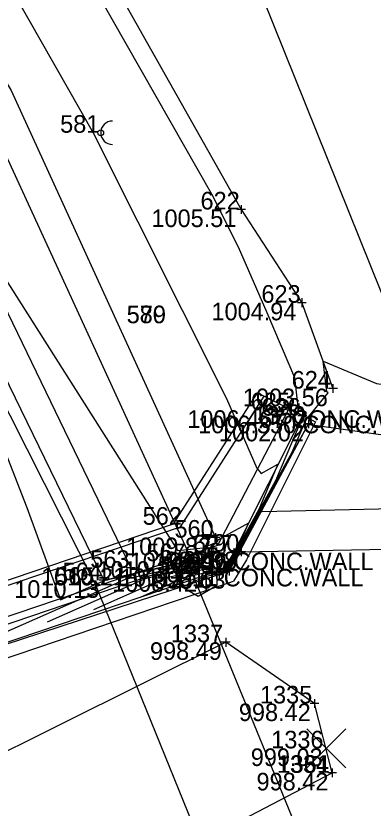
# Model space of a CAD drawing. Extents: x 2354693 to 2355622, y 637071 to 710080.
# Drawn here: x 2355337.5 to 2355361.9, y 709334.6 to 709388.6 of the extents above; entities that cross this region are included whole.
import ezdxf

# ---------------------------------------------------------------- set-up
doc = ezdxf.new("R2010")
doc.units = 0
for name, color, linetype in [('BR_X_Sub_Foot_Object', 7, 'Continuous'), ('BR_X_SV_Abut', 7, 'Continuous'), ('BR_X_SV_Beam_Seat', 7, 'Continuous'), ('DT_X_Contour_Major', 7, 'Continuous'), ('DT_X_Contour_Minor', 7, 'Continuous'), ('HY_X_Water_Edge', 7, 'Continuous'), ('PM_X_Surveyed_Line', 7, 'Continuous'), ('PV_X_EOP', 7, 'Continuous'), ('PV_X_Shoulder', 7, 'Continuous'), ('RD_X_Cells', 7, 'Continuous'), ('RD_X_GR_Lt', 7, 'Continuous'), ('SV_X_Break_Lines', 7, 'Continuous'), ('SV_X_Random_Point', 7, 'Continuous'), ('SV_X_Shot_Marker', 7, 'Continuous'), ('SV_X_Text_Comment', 7, 'Continuous'), ('SV_X_Text_Elevation', 7, 'Continuous'), ('SV_X_Text_Name', 7, 'Continuous'), ('SV_X_Toe_of_Slope', 7, 'Continuous'), ('SV_X_Top_of_Bank', 7, 'Continuous'), ('UT_X_Misc_Cells', 7, 'Continuous'), ('UT_X_Telecom', 7, 'Continuous')]:
    doc.layers.add(name, color=color, linetype=linetype)

msp = doc.modelspace()

# ---------------------------------------------------------------- linework, layer by layer
at = {"layer": 'BR_X_Sub_Foot_Object'}
for p, q in [((2355348.286, 709353.939), (2355354.026, 709362.886)), ((2355348.756, 709353.746), (2355354.475, 709362.661)), ((2355354.026, 709362.886), (2355357.991, 709360.898)), ((2355320.058, 709344.378), (2355348.286, 709353.939)), ((2355319.807, 709343.941), (2355348.756, 709353.746)), ((2355320.484, 709339.244), (2355352.382, 709350.047))]:
    msp.add_line(p, q, dxfattribs=at)
msp.add_lwpolyline([(2355357.991, 709360.898), (2355353.278, 709351.501), (2355352.382, 709350.047)], dxfattribs=at)
at = {"layer": 'BR_X_SV_Abut'}
for p, q in [((2355351.31, 709352.499), (2355356.173, 709361.771)), ((2355319.736, 709341.806), (2355351.31, 709352.499)), ((2355319.789, 709341.296), (2355351.346, 709351.984)), ((2355320.164, 709340.191), (2355351.72, 709350.879))]:
    msp.add_line(p, q, dxfattribs=at)
msp.add_lwpolyline([(2355356.328, 709361.694), (2355357.086, 709361.324), (2355352.404, 709351.988), (2355351.72, 709350.879)], dxfattribs=at)
at = {"layer": 'BR_X_SV_Beam_Seat'}
for p, q in [((2355352.404, 709352.288), (2355352.404, 709351.688)), ((2355352.704, 709351.988), (2355352.104, 709351.988)), ((2355351.222, 709350.815), (2355351.222, 709350.215)), ((2355351.522, 709350.515), (2355350.922, 709350.515))]:
    msp.add_line(p, q, dxfattribs=at)
at = {"layer": 'DT_X_Contour_Major'}
for points in [[(2355329.768, 709376.874), (2355338.272, 709355.053), (2355340.574, 709348.757), (2355343.616, 709350.102)], [(2355329.768, 709376.874), (2355338.272, 709355.053), (2355340.574, 709348.757), (2355343.616, 709350.102)], [(2355343.616, 709350.102), (2355349.258, 709351.382), (2355351.694, 709350.839), (2355351.75, 709350.866), (2355352.378, 709351.887), (2355352.97, 709352.962), (2355353.407, 709353.989), (2355351.34, 709352.861), (2355351.242, 709352.706), (2355350.295, 709352.289), (2355348.6, 709352.094), (2355333.866, 709375.297)], [(2355343.616, 709350.102), (2355349.258, 709351.382), (2355351.694, 709350.839), (2355351.75, 709350.866), (2355352.378, 709351.887), (2355352.97, 709352.962), (2355353.407, 709353.989), (2355351.34, 709352.861), (2355351.242, 709352.706), (2355350.295, 709352.289), (2355348.6, 709352.094), (2355333.866, 709375.297)], [(2355349.216, 709349.807), (2355350.46, 709350.357), (2355351.14, 709350.511), (2355351.433, 709350.446), (2355352.043, 709350.744), (2355352.119, 709350.867), (2355354.278, 709354.787), (2355354.352, 709354.784), (2355372.217, 709355.195), (2355377.397, 709354.455), (2355381.095, 709354.556), (2355411.836, 709365.805), (2355413.019, 709366.158), (2355415.355, 709371.884), (2355426.88, 709369.542), (2355418.722, 709358.718)], [(2355349.216, 709349.807), (2355350.46, 709350.357), (2355351.14, 709350.511), (2355351.433, 709350.446), (2355352.043, 709350.744), (2355352.119, 709350.867), (2355354.278, 709354.787), (2355354.352, 709354.784), (2355372.217, 709355.195), (2355377.397, 709354.455), (2355381.095, 709354.556), (2355411.836, 709365.805), (2355413.019, 709366.158), (2355415.355, 709371.884), (2355426.88, 709369.542), (2355418.722, 709358.718)]]:
    msp.add_lwpolyline(points, dxfattribs=at)
at = {"layer": 'DT_X_Contour_Minor'}
for points in [[(2355256.514, 709490.43), (2355283.775, 709461.072), (2355292.628, 709451.208), (2355294.845, 709448.841), (2355297.747, 709446.107), (2355326.872, 709414.967), (2355331.388, 709409.92), (2355333.438, 709407.016), (2355350.907, 709376.422), (2355352.705, 709372.844), (2355354.66, 709368.362), (2355356.548, 709363.933), (2355356.786, 709361.932), (2355357.348, 709361.556), (2355357.12, 709361.279), (2355355.247, 709356.875), (2355352.274, 709351.479), (2355351.867, 709350.817), (2355351.589, 709350.682), (2355350.011, 709351.034), (2355346.353, 709350.204), (2355339.665, 709347.247)], [(2355256.514, 709490.43), (2355283.775, 709461.072), (2355292.628, 709451.208), (2355294.845, 709448.841), (2355297.747, 709446.107), (2355326.872, 709414.967), (2355331.388, 709409.92), (2355333.438, 709407.016), (2355350.907, 709376.422), (2355352.705, 709372.844), (2355354.66, 709368.362), (2355356.548, 709363.933), (2355356.786, 709361.932), (2355357.348, 709361.556), (2355357.12, 709361.279), (2355355.247, 709356.875), (2355352.274, 709351.479), (2355351.867, 709350.817), (2355351.589, 709350.682), (2355350.011, 709351.034), (2355346.353, 709350.204), (2355339.665, 709347.247)], [(2355255.69, 709482.934), (2355288.364, 709446.527), (2355296.545, 709437.792), (2355301.822, 709432.821), (2355307.383, 709427.211), (2355308.607, 709426.123), (2355326.354, 709406.292), (2355335.671, 709393.094), (2355342.795, 709380.617), (2355351.9, 709362.495), (2355353.976, 709357.738), (2355354.28, 709357.384), (2355355.423, 709358.007), (2355354.109, 709354.918), (2355352.326, 709351.683), (2355351.808, 709350.842), (2355351.641, 709350.76), (2355349.634, 709351.208), (2355344.985, 709350.153), (2355336.482, 709346.393)], [(2355255.69, 709482.934), (2355288.364, 709446.527), (2355296.545, 709437.792), (2355301.822, 709432.821), (2355307.383, 709427.211), (2355308.607, 709426.123), (2355326.354, 709406.292), (2355335.671, 709393.094), (2355342.795, 709380.617), (2355351.9, 709362.495), (2355353.976, 709357.738), (2355354.28, 709357.384), (2355355.423, 709358.007), (2355354.109, 709354.918), (2355352.326, 709351.683), (2355351.808, 709350.842), (2355351.641, 709350.76), (2355349.634, 709351.208), (2355344.985, 709350.153), (2355336.482, 709346.393)], [(2355346.033, 709348.954), (2355349.091, 709350.306), (2355350.763, 709350.685), (2355351.485, 709350.524), (2355351.985, 709350.769), (2355352.171, 709351.071), (2355357.489, 709360.726), (2355357.49, 709360.726), (2355357.63, 709360.729), (2355373.499, 709358.462), (2355384.828, 709358.77), (2355406.085, 709366.548), (2355412.097, 709368.343), (2355414.408, 709374.007), (2355418.626, 709378.122), (2355431.615, 709394.262), (2355434.67, 709399.067), (2355441.725, 709407.886)], [(2355346.033, 709348.954), (2355349.091, 709350.306), (2355350.763, 709350.685), (2355351.485, 709350.524), (2355351.985, 709350.769), (2355352.171, 709351.071), (2355357.489, 709360.726), (2355357.49, 709360.726), (2355357.63, 709360.729), (2355373.499, 709358.462), (2355384.828, 709358.77), (2355406.085, 709366.548), (2355412.097, 709368.343), (2355414.408, 709374.007), (2355418.626, 709378.122), (2355431.615, 709394.262), (2355434.67, 709399.067), (2355441.725, 709407.886)], [(2355342.849, 709348.1), (2355347.722, 709350.255), (2355350.387, 709350.859), (2355351.537, 709350.603), (2355351.926, 709350.793), (2355352.223, 709351.275), (2355356.385, 709358.831), (2355357.318, 709361.025), (2355358.848, 709362.883), (2355358.748, 709362.951), (2355358.5, 709365.034), (2355362.15, 709363.512), (2355364.815, 709363.153), (2355369.602, 709362.469), (2355388.561, 709362.984), (2355400.334, 709367.291), (2355411.176, 709370.528), (2355412.756, 709374.401), (2355421.504, 709382.936), (2355430.17, 709393.705), (2355436.389, 709403.486)], [(2355342.849, 709348.1), (2355347.722, 709350.255), (2355350.387, 709350.859), (2355351.537, 709350.603), (2355351.926, 709350.793), (2355352.223, 709351.275), (2355356.385, 709358.831), (2355357.318, 709361.025), (2355358.848, 709362.883), (2355358.748, 709362.951), (2355358.5, 709365.034), (2355362.15, 709363.512), (2355364.815, 709363.153), (2355369.602, 709362.469), (2355388.561, 709362.984), (2355400.334, 709367.291), (2355411.176, 709370.528), (2355412.756, 709374.401), (2355421.504, 709382.936), (2355430.17, 709393.705), (2355436.389, 709403.486)]]:
    msp.add_lwpolyline(points, dxfattribs=at)
at = {"layer": 'HY_X_Water_Edge'}
for points in [[(2355352.907, 709352.047), (2355379.285, 709352.514), (2355413.245, 709365.623), (2355415.947, 709373.639), (2355433.01, 709394.801), (2355445.631, 709410.589)], [(2355359.12, 709336.962), (2355357.913, 709341.692), (2355351.852, 709345.867), (2355323.23, 709331.642), (2355296.554, 709310.152), (2355279.902, 709286.977), (2355296.129, 709295.23), (2355310.102, 709295.061), (2355327.095, 709303.904), (2355323.879, 709317.989), (2355329.602, 709321.567), (2355359.12, 709336.962)]]:
    msp.add_lwpolyline(points, dxfattribs=at)
at = {"layer": 'PM_X_Surveyed_Line'}
msp.add_lwpolyline([(2355180.148, 709561.237), (2355214.753, 709522.888), (2355249.307, 709484.271), (2355284.017, 709443.142), (2355315.552, 709399.77), (2355328.888, 709377.573), (2355342.967, 709349.789), (2355353.365, 709324.191), (2355361.351, 709299.648), (2355367.764, 709272.473), (2355372.191, 709243.487), (2355373.87, 709217.884), (2355371.213, 709164.414), (2355367.135, 709139.625), (2355360.061, 709111.877), (2355351.618, 709085.78), (2355342.505, 709062.338), (2355329.445, 709031.419), (2355320.624, 709012.583)], dxfattribs=at)
at = {"layer": 'PV_X_EOP'}
msp.add_lwpolyline([(2355180.814, 709561.741), (2355215.64, 709523.556), (2355249.922, 709484.356), (2355284.407, 709443.36), (2355315.939, 709399.966), (2355329.751, 709378.355), (2355343.524, 709350.098), (2355349.219, 709351.4), (2355359.304, 709326.795), (2355367.588, 709301.754), (2355374.108, 709275.907), (2355368.17, 709272.694), (2355372.498, 709243.563), (2355374.502, 709217.665), (2355371.414, 709164.432), (2355367.842, 709139.325), (2355361.02, 709111.642), (2355352.388, 709085.56), (2355343.445, 709061.967), (2355330.49, 709031.083), (2355321.141, 709011.801)], dxfattribs=at)
at = {"layer": 'PV_X_Shoulder'}
msp.add_lwpolyline([(2355182.191, 709563.218), (2355217.156, 709524.646), (2355251.587, 709486.128), (2355286.914, 709444.936), (2355318.238, 709401.514), (2355331.465, 709379.667), (2355345.367, 709350.943)], dxfattribs=at)
at = {"layer": 'RD_X_Cells'}
msp.add_lwpolyline([(2355348.682, 709349.774), (2355349.98, 709349.024), (2355351.278, 709349.774), (2355351.278, 709351.274), (2355349.98, 709352.024), (2355348.682, 709351.274), (2355348.682, 709349.774)], dxfattribs=at)
at = {"layer": 'RD_X_GR_Lt'}
msp.add_lwpolyline([(2355298.604, 709438.975), (2355313.711, 709417.638), (2355322.758, 709404.112), (2355335.403, 709382.171), (2355349.98, 709350.524)], dxfattribs=at)
at = {"layer": 'SV_X_Break_Lines'}
msp.add_lwpolyline([(2355313.178, 709343.449), (2355320.081, 709340.268), (2355352.083, 709350.728), (2355357.514, 709360.772)], dxfattribs=at)
at = {"layer": 'SV_X_Random_Point'}
for p, q in [((2355357.384, 709337.293), (2355360.051, 709339.963)), ((2355357.384, 709339.963), (2355360.051, 709337.293))]:
    msp.add_line(p, q, dxfattribs=at)
at = {"layer": 'SV_X_Shot_Marker'}
for p, q in [((2355352.903, 709375.69), (2355352.903, 709375.09)), ((2355353.203, 709375.39), (2355352.603, 709375.39)), ((2355357.35, 709369.03), (2355356.75, 709369.03)), ((2355357.05, 709369.33), (2355357.05, 709368.73)), ((2355359.476, 709363.173), (2355358.876, 709363.173)), ((2355359.176, 709363.473), (2355359.176, 709362.873)), ((2355356.328, 709361.994), (2355356.328, 709361.394)), ((2355356.328, 709361.994), (2355356.328, 709361.394)), ((2355356.628, 709361.694), (2355356.028, 709361.694)), ((2355356.628, 709361.694), (2355356.028, 709361.694)), ((2355357.086, 709361.624), (2355357.086, 709361.024)), ((2355357.086, 709361.624), (2355357.086, 709361.024)), ((2355357.386, 709361.324), (2355356.786, 709361.324)), ((2355357.386, 709361.324), (2355356.786, 709361.324)), ((2355357.514, 709361.073), (2355357.514, 709360.472)), ((2355357.814, 709360.772), (2355357.214, 709360.772)), ((2355351.163, 709353.306), (2355351.163, 709352.706)), ((2355351.463, 709353.006), (2355350.863, 709353.006)), ((2355351.16, 709352.236), (2355350.56, 709352.236)), ((2355351.266, 709352.277), (2355350.666, 709352.277)), ((2355350.86, 709352.536), (2355350.86, 709351.936)), ((2355350.966, 709352.577), (2355350.966, 709351.977)), ((2355352.404, 709352.288), (2355352.404, 709351.688)), ((2355352.907, 709352.347), (2355352.907, 709351.747)), ((2355349.219, 709351.7), (2355349.219, 709351.1)), ((2355349.289, 709351.84), (2355349.289, 709351.24)), ((2355352.704, 709351.988), (2355352.104, 709351.988)), ((2355353.207, 709352.047), (2355352.607, 709352.047)), ((2355345.367, 709351.243), (2355345.367, 709350.643)), ((2355349.519, 709351.4), (2355348.919, 709351.4)), ((2355349.589, 709351.54), (2355348.989, 709351.54)), ((2355351.72, 709351.179), (2355351.72, 709350.579)), ((2355351.72, 709351.179), (2355351.72, 709350.579)), ((2355345.667, 709350.943), (2355345.067, 709350.943)), ((2355351.416, 709350.779), (2355351.416, 709350.178)), ((2355351.416, 709350.779), (2355351.416, 709350.178)), ((2355352.02, 709350.879), (2355351.42, 709350.879)), ((2355352.02, 709350.879), (2355351.42, 709350.879)), ((2355352.383, 709350.728), (2355351.783, 709350.728)), ((2355352.083, 709351.028), (2355352.083, 709350.428)), ((2355342.967, 709350.089), (2355342.967, 709349.489)), ((2355343.824, 709350.098), (2355343.224, 709350.098)), ((2355343.524, 709350.398), (2355343.524, 709349.798)), ((2355351.716, 709350.478), (2355351.116, 709350.478)), ((2355351.716, 709350.478), (2355351.116, 709350.478)), ((2355343.267, 709349.789), (2355342.667, 709349.789)), ((2355352.152, 709345.867), (2355351.552, 709345.867)), ((2355351.852, 709346.167), (2355351.852, 709345.567)), ((2355357.913, 709341.992), (2355357.913, 709341.392)), ((2355358.213, 709341.692), (2355357.613, 709341.692)), ((2355359.12, 709337.262), (2355359.12, 709336.662)), ((2355359.12, 709337.262), (2355359.12, 709336.662)), ((2355359.42, 709336.962), (2355358.82, 709336.962)), ((2355359.42, 709336.962), (2355358.82, 709336.962))]:
    msp.add_line(p, q, dxfattribs=at)
at = {"layer": 'SV_X_Toe_of_Slope'}
for points in [[(2355187.561, 709568.549), (2355223.434, 709529.363), (2355257.658, 709491.428), (2355294.213, 709452.947), (2355332.808, 709410.944), (2355352.903, 709375.39), (2355357.05, 709369.03), (2355359.176, 709363.173)], [(2355352.907, 709352.047), (2355379.285, 709352.514), (2355413.245, 709365.623), (2355415.947, 709373.639), (2355433.01, 709394.801), (2355445.631, 709410.589)], [(2355359.12, 709336.962), (2355357.913, 709341.692), (2355351.852, 709345.867), (2355323.23, 709331.642), (2355296.554, 709310.152), (2355279.902, 709286.977), (2355296.129, 709295.23), (2355310.102, 709295.061), (2355327.095, 709303.904), (2355323.879, 709317.989), (2355329.602, 709321.567), (2355359.12, 709336.962)]]:
    msp.add_lwpolyline(points, dxfattribs=at)
at = {"layer": 'SV_X_Top_of_Bank'}
msp.add_lwpolyline([(2355296.627, 709437.256), (2355306.813, 709428.559), (2355324.299, 709404.811), (2355337.209, 709383.506), (2355351.163, 709353.006)], dxfattribs=at)
at = {"layer": 'UT_X_Misc_Cells'}
msp.add_circle((2355343.319, 709380.623), 0.2, dxfattribs=at)
msp.add_arc((2355344.119, 709380.623), 0.8, 90, 270, dxfattribs=at)
at = {"layer": 'UT_X_Telecom'}
msp.add_line((2355345.904, 709410.895), (2355420.443, 709225.551), dxfattribs=at)

# ---------------------------------------------------------------- texts
at = {"layer": 'BR_X_SV_Beam_Seat'}
for s, p in [('627', (2355349.617, 709351.988)), ('1010.996', (2355345.296, 709350.788)), ('1330', (2355347.456, 709350.515)), ('CONC.WALL', (2355352.404, 709350.788)), ('1008.424', (2355344.094, 709349.315))]:
    msp.add_text(s, height=1.2, dxfattribs=at).set_placement(p)
at = {"layer": 'SV_X_Text_Comment'}
for p in [(2355356.328, 709360.494), (2355357.086, 709360.124), (2355351.72, 709349.679)]:
    msp.add_text('CONC.WALL', height=1.2, dxfattribs=at).set_placement(p)
at = {"layer": 'SV_X_Text_Elevation'}
for s, p in [('1005.51', (2355346.781, 709374.19)), ('1004.94', (2355350.88, 709367.83)), ('1003.56', (2355353.026, 709361.973)), ('1006.467', (2355349.233, 709360.494)), ('1006.350', (2355349.969, 709360.124)), ('1002.02', (2355351.395, 709359.573)), ('1009.83', (2355345.054, 709351.806)), ('999.08', (2355347.718, 709350.847)), ('1010.21', (2355343.098, 709350.2)), ('1010.21', (2355339.246, 709349.743)), ('1011.011', (2355344.64, 709349.679)), ('998.63', (2355346.932, 709349.528)), ('1010.13', (2355337.415, 709348.898)), ('998.49', (2355346.681, 709344.667)), ('998.42', (2355352.751, 709340.492)), ('999.03', (2355353.566, 709337.428)), ('998.42', (2355353.958, 709335.762)), ('998.42', (2355353.958, 709335.762))]:
    msp.add_text(s, height=1.2, dxfattribs=at).set_placement(p)
at = {"layer": 'SV_X_Text_Name'}
for s, p in [('581', (2355340.548, 709380.623)), ('622', (2355350.134, 709375.39)), ('623', (2355354.291, 709369.03)), ('580', (2355345.087, 709367.633)), ('579', (2355345.098, 709367.629)), ('624', (2355356.357, 709363.173)), ('625', (2355353.565, 709361.694)), ('626', (2355354.287, 709361.324)), ('1350', (2355353.749, 709360.772)), ('562', (2355346.183, 709353.885)), ('560', (2355348.355, 709353.006)), ('790', (2355350.099, 709352.047)), ('567', (2355346.433, 709351.4)), ('563', (2355342.609, 709350.943)), ('561', (2355347.209, 709350.524)), ('1349', (2355348.348, 709350.728)), ('628', (2355348.924, 709350.879)), ('564', (2355340.705, 709350.098)), ('565', (2355340.205, 709349.789)), ('1337', (2355348.108, 709345.867)), ('1335', (2355354.192, 709341.692)), ('1336', (2355354.961, 709338.628)), ('1334', (2355355.343, 709336.962)), ('1361', (2355355.391, 709336.962))]:
    msp.add_text(s, height=1.2, dxfattribs=at).set_placement(p)

doc.saveas('drawing.dxf')
